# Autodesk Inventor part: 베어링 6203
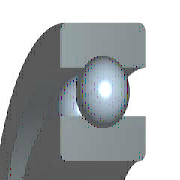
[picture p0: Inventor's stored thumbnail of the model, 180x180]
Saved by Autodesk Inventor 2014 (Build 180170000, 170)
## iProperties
IsCustomPart: 1
Created: 2012-02
Part Number: 베어링 6203
Material: 강철, 연강
Description: 깊은 그루브 볼 베어링
Document SubType Name: Modeling
Standard: KS B 2023
Designer: mduedu
Standards Organization: KS
Language: ko-KR
Size Designation: 6203 - 17 x 40 x 12
Categories: <MemberInstance><Categories><Category DisplayName="샤프트 부품" InternalName="7f7aeb1f-a693-4053-b835-cee3144e0d98" Mnemonic="SHFT"><Category DisplayName="베어링" Inter
Density: 1 g/cm^3
Appearance: 노란색
Author: mduedu
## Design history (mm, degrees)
sketch "스케치" dims "d0" = 5.98 (= -0.26 x WD + 0.26 x BD)
  geometry: L1 (3.01, 14.25)-(8.99, 14.25); L2 (6, 14.25)-(6, 11.26); L3 (6, 14.25)-(6, 17.24); L4 (3.778, 12.249)-(0, 12.249); L5 (0, 8.5)-(12, 8.5); L6 (3.778, 16.251)-(0, 16.251); L7 (0, 20)-(12, 20); L8 (12, 8.5)-(12, 12.249); L9 (8.222, 12.249)-(12, 12.249); L10 (8.222, 16.251)-(12, 16.251); L11 (12, 20)-(12, 16.251); L12 (-1.4, 0)-(8.4, 0) reference; L13 (0, -0.3)-(0, 5.3) reference
  constraints: 22 end point, 4 point on line, 2 collinear, 2 perpendicular, 2 symmetric about line, 1 midpoint, 1 parallel, 14 other
  dimensions: "d9" = 17 diameter of L5 L12 (= WD); "d11" = 40 diameter of L7 L12 (= BD); "d12" = 12 distance between parallel lines of L8 L13 (= KB); "d13" = 24.498 diameter of L9 L12 (= 0.326 x BD + 0.674 x WD)
revolve "본체" stored, may be unused: angle "d6" = 90 deg
revolve "볼" stored, may be unused: angle "d7" = 90 deg
pattern_circular "IDS_ARRAYBALL[SIMPL:T]" dims angle "d3" = 360 deg
body "Solid1"
fillet "모깎기1" dims "d1" = 0.6 (= KRS)
other parameters: "WD" = 17 [user parameter; used in 5 equation terms], "BD" = 40 [user parameter; used in 5 equation terms], "KB" = 12 [user parameter; used in 1 equation term], "KRS" = 0.6 [user parameter; used in 1 equation term], "d4" = 0, "d5" = 0, "d8" = 0, "d14" = 0, "d15" = 0, "BBA" = 0 [user parameter], "BC0" = 4750000 [user parameter], "BC" = 9560000 [user parameter], "WR" = 8.5 (= 0.5 x WD) [user parameter]
